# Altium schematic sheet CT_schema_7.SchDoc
size 235 x 258 mm
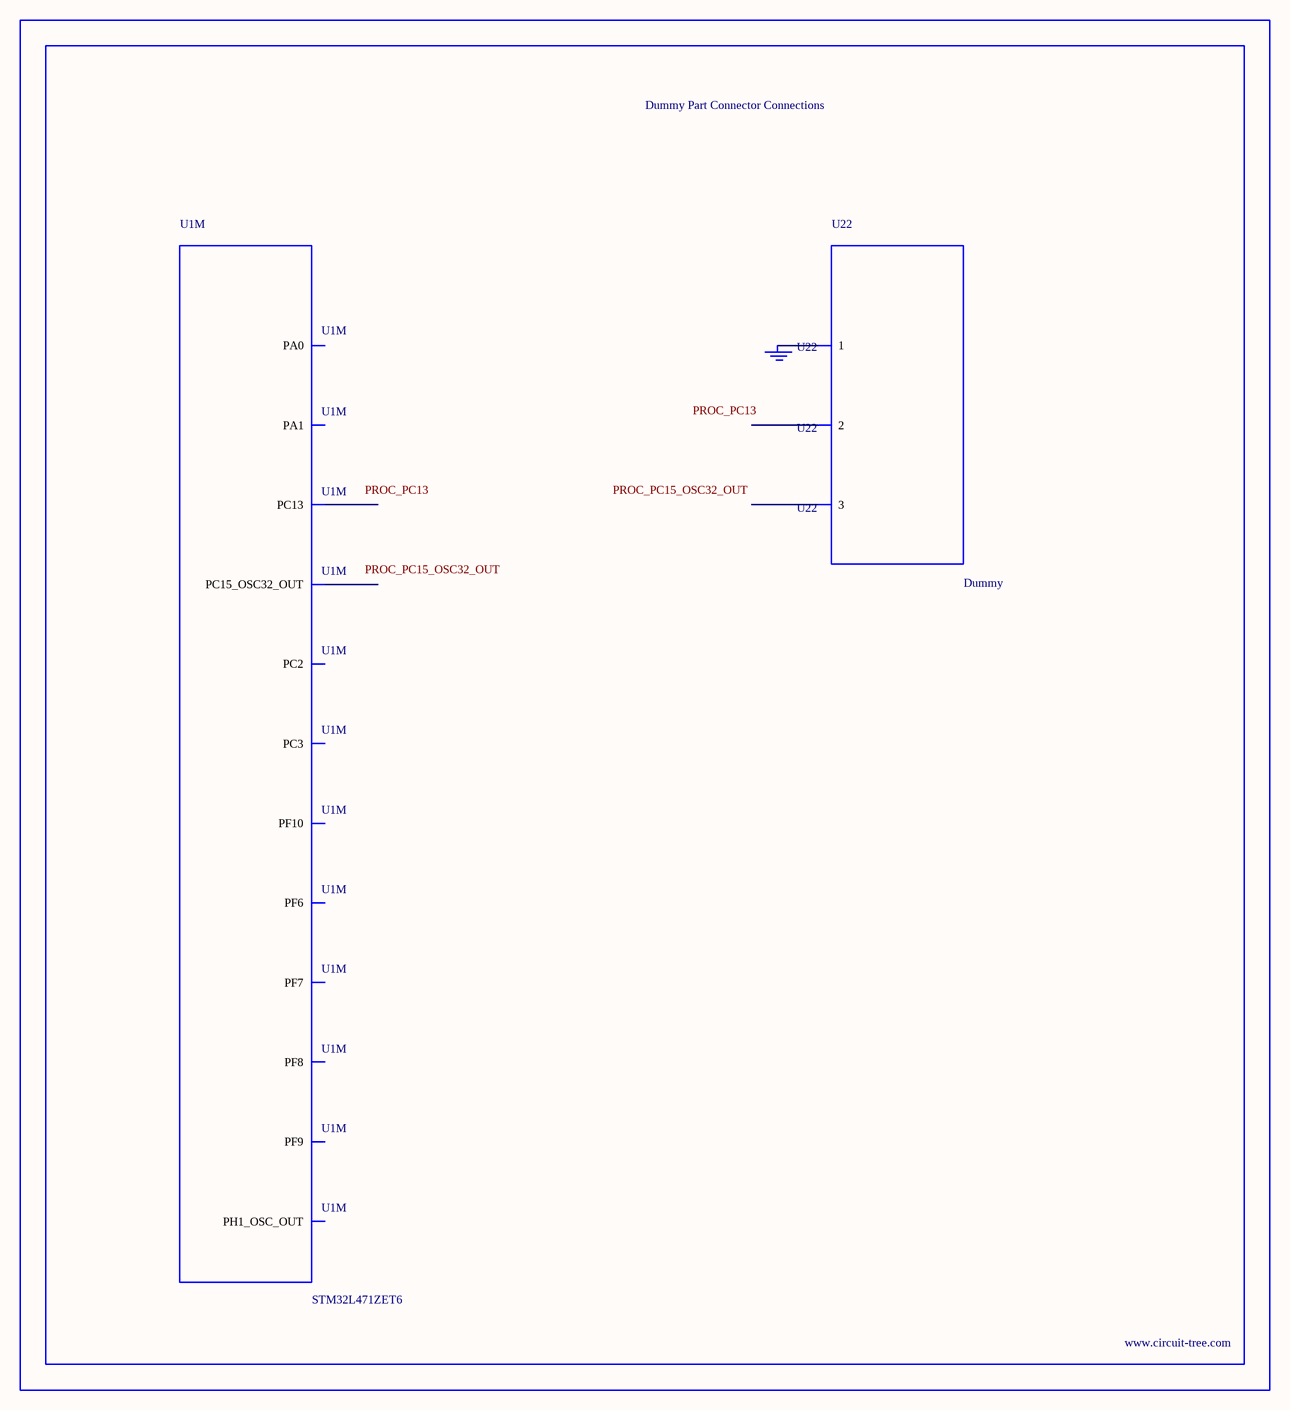
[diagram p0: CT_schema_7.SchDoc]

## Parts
BORDER6  (no value)
GND_INSTANCE_6_0  (no value)
U1  STM32L471ZET6  [LQFP144]  (part M of 13)
U22  Dummy  [DUMMY_PACKAGE_204]

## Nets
NetGND_INSTANCE_6_0_0: GND_INSTANCE_6_0.0(GND) U22.1

Not connected (* = marked no-connect by the designer): U1 7(PC13) 9(PC15_OSC32_OUT) 18(PF6) 19(PF7) 20(PF8) 21(PF9) 22(PF10) 24(PH1_OSC_OUT) 28(PC2) 29(PC3) 34(PA0) 35(PA1); U22 2 3

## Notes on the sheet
- Labels drawn without touching a wire or pin: PROC_PC13, PROC_PC15_OSC32_OUT

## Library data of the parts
BORDER6 = BORDER_PAGE6
GND_INSTANCE_6_0 = GND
